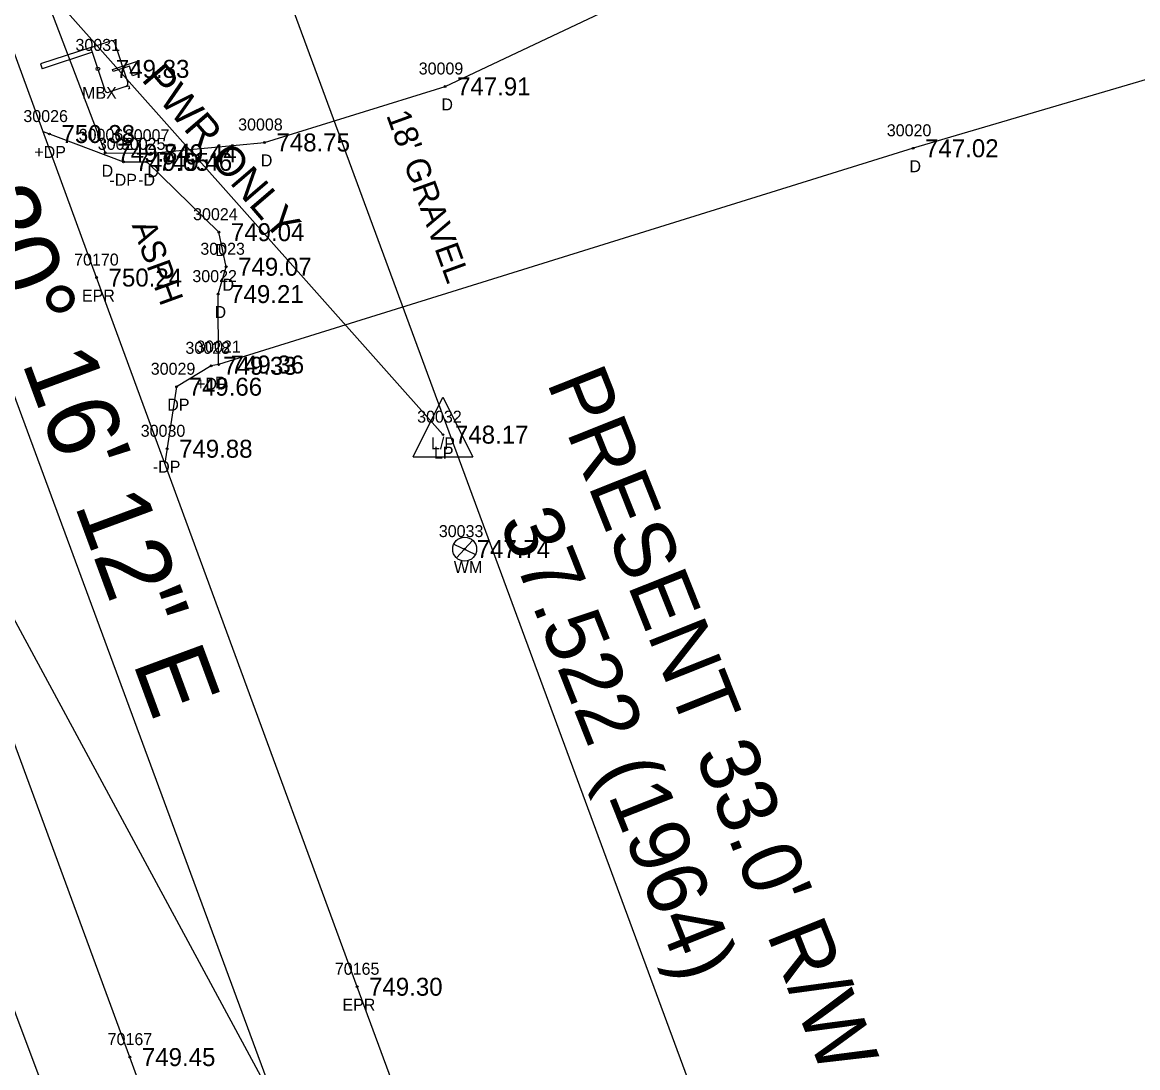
# Model space of a CAD drawing. Extents: x 1375131 to 1378678, y 999028 to 1004053.
# Drawn here: x 1376716.1 to 1376809.2, y 1002844.1 to 1002931.4 of the extents above; entities that cross this region are included whole.
import ezdxf

# ---------------------------------------------------------------- set-up
doc = ezdxf.new("R2010")
doc.units = 0
for name, color, linetype in [('RD_EX_BldgApp', 7, 'Continuous'), ('RD_EX_BldgApp_txCode', 7, 'Continuous'), ('RD_EX_Driveway', 7, 'Continuous'), ('RD_EX_Driveway_txCode', 7, 'Continuous'), ('RD_EX_H2O', 7, 'Continuous'), ('RD_EX_Road', 7, 'Continuous'), ('RD_EX_Road_txCode', 7, 'Continuous'), ('RD_EX_RW', 7, 'Continuous'), ('RD_EX_RW_TX', 7, 'Continuous'), ('RD_EX_SU_Elec', 7, 'Continuous'), ('RD_EX_TX_BldgApp_ELEV', 7, 'Continuous'), ('RD_EX_TX_Driveway_ELEV', 7, 'Continuous'), ('RD_EX_TX_Road_ELEV', 7, 'Continuous'), ('RD_EX_TX_UT_ELEV', 7, 'Continuous'), ('RD_EX_UT', 7, 'Continuous'), ('RD_EX_UT_txCode', 7, 'Continuous'), ('RD_HC_Cl', 7, 'Continuous'), ('RD_HC_Data', 7, 'Continuous'), ('RD_SMD_Locator', 7, 'Continuous'), ('RD_TX_Misc2', 7, 'Continuous'), ('RD_TX_Utilities', 7, 'Continuous')]:
    doc.layers.add(name, color=color, linetype=linetype)

msp = doc.modelspace()

# ---------------------------------------------------------------- linework, layer by layer
at = {"layer": 'RD_EX_BldgApp'}
for p, q in [((1376721.838, 1002929.264), (1376723.499, 1002929.814)), ((1376721.838, 1002929.264), (1376717.651, 1002927.877)), ((1376721.97, 1002928.866), (1376717.782, 1002927.48)), ((1376723.028, 1002925.672), (1376721.838, 1002929.264)), ((1376723.815, 1002929.655), (1376724.925, 1002926.301)), ((1376717.651, 1002927.877), (1376717.782, 1002927.48)), ((1376723.652, 1002927.419), (1376725.64, 1002928.078)), ((1376725.64, 1002928.078), (1376725.963, 1002927.102)), ((1376723.712, 1002927.239), (1376723.652, 1002927.419)), ((1376725.061, 1002927.686), (1376723.712, 1002927.239)), ((1376725.324, 1002926.891), (1376725.061, 1002927.686)), ((1376725.963, 1002927.102), (1376725.324, 1002926.891)), ((1376724.767, 1002925.985), (1376725.004, 1002926.063)), ((1376725.004, 1002926.063), (1376725.083, 1002925.826)), ((1376724.767, 1002925.985), (1376723.344, 1002925.513)), ((1376725.083, 1002925.826), (1376724.964, 1002925.787))]:
    msp.add_line(p, q, dxfattribs=at)
for centre, start, end in [((1376723.577, 1002929.576), 18.32339, 108.32339), ((1376724.688, 1002926.222), 288.32339, 18.32339), ((1376723.265, 1002925.751), 198.32339, 288.32339)]:
    msp.add_arc(centre, 0.25, start, end, dxfattribs=at)
at = {"layer": 'RD_EX_Driveway'}
for points in [[(1376706.507, 1002954.761), (1376715.388, 1002940.545), (1376723.048, 1002920.461), (1376726.876, 1002920.427), (1376736.336, 1002921.326), (1376751.407, 1002925.999), (1376775.28, 1002937.302), (1376791.557, 1002941.719), (1376806.993, 1002947.414)], [(1376811.924, 1002927.16), (1376790.475, 1002920.841), (1376732.511, 1002902.788), (1376732.473, 1002908.669), (1376733.139, 1002910.95), (1376732.534, 1002913.836), (1376726.506, 1002919.709)], [(1376717.861, 1002922.228), (1376724.579, 1002919.706), (1376726.506, 1002919.709)], [(1376732.511, 1002902.788), (1376731.894, 1002902.682), (1376729.001, 1002900.936), (1376728.017, 1002894.545)]]:
    msp.add_lwpolyline(points, dxfattribs=at)
at = {"layer": 'RD_EX_H2O'}
msp.add_lwpolyline([(1376884.041, 1002432.097), (1376867.958, 1002466.268), (1376845.473, 1002511.575), (1376827.215, 1002560.377), (1376806.483, 1002611.175), (1376788.408, 1002651.649), (1376772.823, 1002694.383), (1376753.279, 1002747.214), (1376736.654, 1002792.885), (1376719.204, 1002838.909), (1376701.081, 1002887.179), (1376684.577, 1002932.846), (1376667.201, 1002979.872)], dxfattribs=at)
at = {"layer": 'RD_EX_Road'}
for points in [[(1376786.564, 1002736.458), (1376786.096, 1002737.56), (1376764.686, 1002794.995), (1376744.066, 1002850.85), (1376722.323, 1002910.048), (1376701.332, 1002967.349), (1376678.413, 1003028.916)], [(1376768.457, 1002728.838), (1376767.881, 1002730.045), (1376746.195, 1002787.097), (1376725.105, 1002844.978), (1376703.802, 1002902.776), (1376682.094, 1002961.906), (1376659.76, 1003022.669)]]:
    msp.add_lwpolyline(points, dxfattribs=at)
at = {"layer": 'RD_EX_RW'}
msp.add_line((1376700.002, 1003037.225), (1376809.218, 1002741.498), dxfattribs=at)
at = {"layer": 'RD_EX_SU_Elec'}
for q in [(1376751.235, 1002896.935), (1376829.238, 1002670.592)]:
    msp.add_line((1376639.019, 1003023.14), q, dxfattribs=at)
at = {"layer": 'RD_EX_UT'}
for p, q in [((1376748.735, 1002895.073), (1376751.235, 1002900.073)), ((1376751.235, 1002900.073), (1376753.735, 1002895.073)), ((1376748.735, 1002895.073), (1376753.735, 1002895.073)), ((1376752.368, 1002886.653), (1376753.702, 1002888.101)), ((1376752.127, 1002887.801), (1376753.943, 1002886.944))]:
    msp.add_line(p, q, dxfattribs=at)
msp.add_circle((1376753.044, 1002887.382), 1, dxfattribs=at)
at = {"layer": 'RD_HC_Cl'}
msp.add_line((1376669.046, 1003025.793), (1376778.262, 1002730.065), dxfattribs=at)
at = {"layer": 'RD_SMD_Locator'}
for centre, radius in [((1376722.433, 1002927.468), 0.15), ((1376751.407, 1002925.999), 0.075), ((1376718.392, 1002922.029), 0.075), ((1376736.336, 1002921.326), 0.075), ((1376723.048, 1002920.461), 0.075), ((1376726.876, 1002920.427), 0.075), ((1376790.475, 1002920.841), 0.075), ((1376724.579, 1002919.706), 0.075), ((1376726.506, 1002919.709), 0.075), ((1376732.534, 1002913.836), 0.075), ((1376733.139, 1002910.95), 0.075), ((1376722.323, 1002910.048), 0.075), ((1376732.473, 1002908.669), 0.075), ((1376731.894, 1002902.682), 0.075), ((1376732.511, 1002902.788), 0.075), ((1376729.001, 1002900.936), 0.075), ((1376751.235, 1002896.935), 0.075), ((1376728.204, 1002895.758), 0.075), ((1376753.044, 1002887.382), 0.075), ((1376744.066, 1002850.85), 0.075), ((1376725.105, 1002844.978), 0.075)]:
    msp.add_circle(centre, radius, dxfattribs=at)

# ---------------------------------------------------------------- texts
at = {"layer": 'RD_EX_BldgApp_txCode'}
for s, p in [('30031', (1376720.559, 1002928.968)), ('MBX', (1376721.11, 1002924.968))]:
    msp.add_text(s, height=1, dxfattribs=at).set_placement(p)
at = {"layer": 'RD_EX_Driveway_txCode'}
for s, p in [('30009', (1376749.21, 1002926.999)), ('D', (1376751.1, 1002923.999)), ('30026', (1376716.211, 1002923.029)), ('30008', (1376734.139, 1002922.326)), ('30006', (1376720.828, 1002921.461)), ('30007', (1376724.679, 1002921.427)), ('30020', (1376788.278, 1002921.841)), ('30027', (1376722.422, 1002920.706)), ('30025', (1376724.349, 1002920.709)), ('+DP', (1376717.124, 1002920.029)), ('D', (1376736.029, 1002919.326)), ('D', (1376790.168, 1002918.841)), ('D', (1376722.741, 1002918.461)), ('-DP', (1376723.39, 1002917.706)), ('-D', (1376725.789, 1002917.709)), ('D', (1376726.569, 1002918.427)), ('30024', (1376730.377, 1002914.836)), ('30023', (1376730.982, 1002911.95)), ('D', (1376732.227, 1002911.836)), ('30022', (1376730.316, 1002909.669)), ('D', (1376732.832, 1002908.95)), ('D', (1376732.166, 1002906.669)), ('30028', (1376729.737, 1002903.682)), ('30021', (1376730.637, 1002903.788)), ('30029', (1376726.844, 1002901.936)), ('D', (1376732.204, 1002900.788)), ('+DP', (1376730.626, 1002900.682)), ('DP', (1376728.221, 1002898.936)), ('30030', (1376726.007, 1002896.758)), ('-DP', (1376727.015, 1002893.758))]:
    msp.add_text(s, height=1, dxfattribs=at).set_placement(p)
at = {"layer": 'RD_EX_Road_txCode'}
for s, p in [('70170', (1376720.449, 1002911.048)), ('EPR', (1376721.095, 1002908.048)), ('70165', (1376742.208, 1002851.85)), ('EPR', (1376742.838, 1002848.85)), ('70167', (1376723.247, 1002845.978))]:
    msp.add_text(s, height=1, dxfattribs=at).set_placement(p)
at = {"layer": 'RD_EX_RW_TX'}
for s, p in [("PRESENT 33.0' R/W", (1376759.86, 1002901.318)), ('37.522 (1964)', (1376755.895, 1002889.655))]:
    msp.add_text(s, height=5, rotation=291.72444, dxfattribs=at).set_placement(p)
at = {"layer": 'RD_EX_TX_BldgApp_ELEV'}
msp.add_text('749.83', height=1.5, dxfattribs=at).set_placement((1376723.933, 1002926.718))
at = {"layer": 'RD_EX_TX_Driveway_ELEV'}
for s, p in [('747.91', (1376752.407, 1002925.249)), ('750.38', (1376719.392, 1002921.279)), ('748.75', (1376737.336, 1002920.576)), ('747.02', (1376791.475, 1002920.091)), ('749.84', (1376724.048, 1002919.711)), ('749.65', (1376725.579, 1002918.956)), ('749.46', (1376727.506, 1002918.959)), ('749.44', (1376727.876, 1002919.677)), ('749.04', (1376733.534, 1002913.086)), ('749.07', (1376734.139, 1002910.2)), ('749.21', (1376733.473, 1002907.919)), ('749.33', (1376732.894, 1002901.932)), ('749.36', (1376733.511, 1002902.038)), ('749.66', (1376730.001, 1002900.186)), ('749.88', (1376729.204, 1002895.008))]:
    msp.add_text(s, height=1.5, dxfattribs=at).set_placement(p)
at = {"layer": 'RD_EX_TX_Road_ELEV'}
for s, p in [('750.24', (1376723.323, 1002909.298)), ('749.30', (1376745.066, 1002850.1)), ('749.45', (1376726.105, 1002844.228))]:
    msp.add_text(s, height=1.5, dxfattribs=at).set_placement(p)
at = {"layer": 'RD_EX_TX_UT_ELEV'}
for s, p in [('748.17', (1376752.235, 1002896.185)), ('747.74', (1376754.044, 1002886.632))]:
    msp.add_text(s, height=1.5, dxfattribs=at).set_placement(p)
at = {"layer": 'RD_EX_UT'}
msp.add_text('L/P', height=1, dxfattribs=at).set_placement((1376750.231, 1002895.714))
at = {"layer": 'RD_EX_UT_txCode'}
for s, p in [('30032', (1376749.078, 1002897.935)), ('LP', (1376750.479, 1002894.935)), ('30033', (1376750.887, 1002888.382)), ('WM', (1376752.138, 1002885.382))]:
    msp.add_text(s, height=1, dxfattribs=at).set_placement(p)
at = {"layer": 'RD_HC_Data'}
msp.add_text('S 20%%d 16\' 12" E', height=6, rotation=290.26995, dxfattribs=at).set_placement((1376708.455, 1002923.555))
at = {"layer": 'RD_TX_Misc2'}
for s, p in [("18' GRAVEL", (1376746.479, 1002923.598)), ('ASPH', (1376725.246, 1002914.411))]:
    msp.add_text(s, height=2, rotation=289.95582, dxfattribs=at).set_placement(p)
at = {"layer": 'RD_TX_Utilities'}
msp.add_text('PWR ONLY', height=2.5, rotation=310.61265, dxfattribs=at).set_placement((1376725.999, 1002926.553))

doc.saveas('drawing.dxf')
